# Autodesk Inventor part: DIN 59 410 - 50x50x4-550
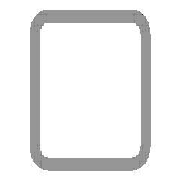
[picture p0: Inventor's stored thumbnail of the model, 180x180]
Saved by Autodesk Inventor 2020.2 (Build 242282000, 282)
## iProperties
Manager: www.cadconsulting.pl
Company: Fabian Stasiak CAD Consulting
Created: 2015-01
Part Number: DIN 59 410 - 50x50x4-550
Material: Stal, miękka
Description: Rurki stalowe o przekroju kwadratowym formowane na gorąco
Document SubType Name: Modellieren
Standard: DIN
Designer: F.Stasiak
Standards Organization: DIN
Language: pl-PL
Size Designation: 50x50x4
Categories: <MemberInstance><Categories><Category DisplayName="Kształtowniki konstrukcyjne" InternalName="089c4875-fa83-4c05-b084-43b9cc11f5ed" Mnemonic="GRDR"><CategoryPar
Stock Number: 50x50x4
Density: 7.85 g/cm^3
Appearance: Częściowo polerowana
Mass: 2999.78 g
Surface Area: 1924.59 cm^2
Volume: 382.138 cm^3
Catalog Web Link: www.expertbooks.pl
_CCFamilyMember: 40
_CCFamilyDisplayName: DIN 59410 (Kwadrat) - Rurki stalowe o przekroju kwadratowym formowane na gorąco
_FrameMemberDoc: Frame Member File
_Version: 15.0.0
_GetPNFromCC: 1
G_W: 50,000 mm
G_H: 50,000 mm
+A09D1646-1770-4303-988D-EFEABC9CCF12+CUTDETAIL1: Wytnij
+0C7F1D2C-6665-4DC1-9BB5-92A0462712D2+CUTDETAIL2: Wytnij
G_L: 550,000 mm
IsCustomPart: 1
Author: F.Stasiak
Subject: Zbiór ćwiczeń. Autodesk Inventor 2020. Kurs Professional
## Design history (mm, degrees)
node "Płaszczyzna początkowa"
node "Płaszczyzna końcowa"
sketch "Szkic"
  geometry: L1 (-17, 25)-(17, 25); L2 (25, 17)-(25, -17); L3 (17, -25)-(-17, -25); L4 (-25, -17)-(-25, 17); L5 (-37.32, 0)-(37.32, 0) reference; L6 (0, -37.32)-(0, 37.32) reference; L7 (-17, 21)-(17, 21); L8 (21, 17)-(21, -17); L9 (17, -21)-(-17, -21); L10 (-21, -17)-(-21, 17); A1 r 8 centre (-17, 17) between (-17, 25) and (-25, 17); A2 r 8 centre (17, 17) between (25, 17) and (17, 25); A3 r 8 centre (17, -17) between (17, -25) and (25, -17); A4 r 8 centre (-17, -17) between (-25, -17) and (-17, -25); A5 r 4 centre (-17, 17) between (-17, 21) and (-21, 17); A6 r 4 centre (17, 17) between (21, 17) and (17, 21); A7 r 4 centre (17, -17) between (17, -21) and (21, -17); A8 r 4 centre (-17, -17) between (-21, -17) and (-17, -21); 3 further points
  constraints: 16 end point, 16 point on circle, 8 centre point, 8 tangent, 6 point on line, 4 parallel, 3 equal radius, 3 perpendicular, 1 horizontal, 7 other
  dimensions: "b" = 50 distance of point (-25, 25) point (25, 25); "msp_r" = 8 radius of A1 (= 2 x ParT); "d8" = 25 distance between parallel lines of L4 L6 (= d9); "d9" = 25 distance between parallel lines of L3 L5 (= 0.5 x b); "d10" = 4 distance between parallel lines of L3 L9 (= ParT)
extrude "Bryła" new body sketch "Szkic" taper "d4" = 0 deg; stored distance "NLG" = 10
node "Driven Length"
  sketch "Sketch2"
    geometry: L1 (0, 0)-(10, 0) reference
    constraints: 2 end point, 1 horizontal
  workplane "Work Plane3"
  sketch "Sketch3"
    geometry: L1 (-2, 25)-(12, 25) reference; L2 (-2, 575)-(12, 575) reference
    dimensions: "d14" = 550 distance between parallel lines of L1 L2 (derived)
node "Płaszczyzna konstrukcyjna4"
feature "Podział1"
node "Płaszczyzna konstrukcyjna5"
feature "Podział2"
body "Solid1"
other parameters: "ParT" = 4, "G_OFFSET_START" = -25 [user parameter; used in 1 equation term], "G_OFFSET_END" = -25 [user parameter; used in 1 equation term], "d11" = 25 (= -G_OFFSET_START), "d12" = 575 (= G_OFFSET_END + B_L), "G_L" = 550 (= d14) [user parameter], "d13" = 90 deg
